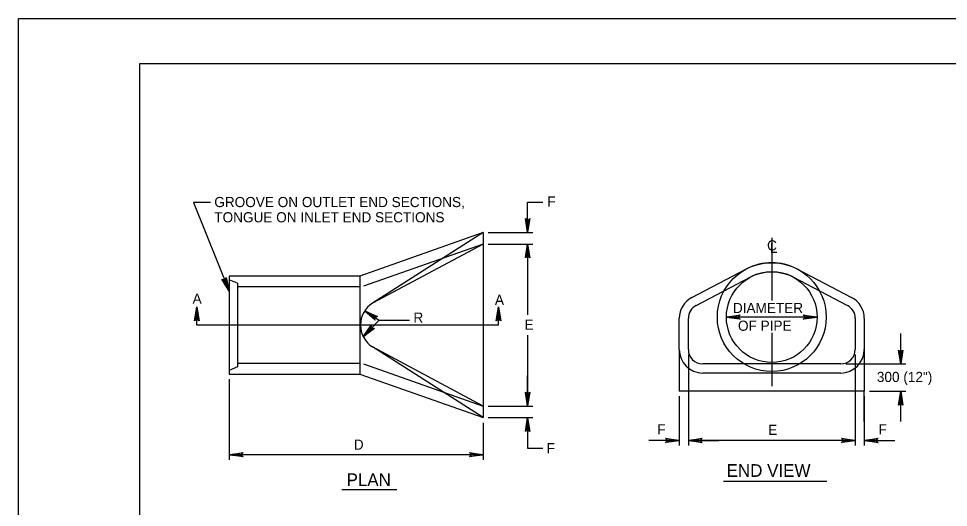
# Model space of a CAD drawing. Extents: x -17 to 888, y -473 to 715.
# Drawn here: x -17.2 to 290.4, y 553.3 to 714.9 of the extents above; entities that cross this region are included whole.
import ezdxf

# ---------------------------------------------------------------- set-up
doc = ezdxf.new("R2010")
doc.units = 0
for name, color, linetype in [('1', 7, 'Continuous'), ('2', 7, 'Continuous'), ('3', 7, 'Continuous'), ('PLT-BNDY', 7, 'Continuous')]:
    doc.layers.add(name, color=color, linetype=linetype)

msp = doc.modelspace()

# ---------------------------------------------------------------- linework, layer by layer
at = {"layer": '1'}
msp.add_lwpolyline([(808.79, 135.89), (808.79, 699.89), (22.79, 699.89), (22.79, 135.89), (808.79, 135.89), (808.79, 162.25), (608.79, 162.25), (608.79, 226.93), (808.79, 226.93), (808.79, 255.89), (608.79, 255.89), (608.79, 135.89), (687.6, 135.89), (687.6, 162.25), (687.6, 135.89), (764.6, 135.89), (764.6, 162.25), (764.6, 149.93), (808.79, 149.93)], dxfattribs=at)
at = {"layer": '2'}
for p, q in [((151.18, 644.17), (151.18, 654.25)), ((136.47, 644.17), (95.67, 629.77)), ((136.47, 644.17), (99.86, 620.83)), ((136.47, 644.17), (136.47, 582.97)), ((138.15, 644.17), (152.86, 644.17)), ((136.47, 640.36), (96.87, 626.38)), ((136.47, 640.36), (99.86, 620.83)), ((138.15, 640.36), (152.86, 640.36)), ((151.18, 640.36), (151.18, 616.93)), ((231.93, 642.4), (231.93, 621.68)), ((205.53, 622.72), (223.61, 632.15)), ((240.26, 632.15), (258.34, 622.72)), ((55.15, 627.37), (52.47, 628.57)), ((206.91, 620.06), (225, 629.49)), ((238.87, 629.49), (256.95, 620.06)), ((41.75, 613.57), (41.75, 619.57)), ((141.53, 613.57), (141.53, 619.57)), ((201.33, 605.51), (201.33, 615.8)), ((204.33, 605.51), (204.33, 615.8)), ((204.33, 605.51), (204.33, 615.8)), ((246.93, 616.19), (216.93, 616.19)), ((259.53, 615.8), (259.53, 605.51)), ((262.53, 615.8), (262.53, 605.51)), ((49.12, 613.57), (41.75, 613.57)), ((137.65, 613.57), (49.12, 613.57)), ((95.67, 613.57), (95.67, 613.57)), ((141.53, 613.57), (137.65, 613.57)), ((151.18, 610.21), (151.18, 586.79)), ((231.93, 611.03), (231.93, 593.4)), ((274.58, 600.71), (274.58, 610.79)), ((136.47, 582.97), (99.86, 606.31)), ((136.47, 586.79), (99.86, 606.31)), ((201.33, 605.51), (201.33, 591.71)), ((204.33, 603.83), (204.33, 573.73)), ((259.53, 603.83), (259.53, 573.73)), ((262.53, 605.51), (262.53, 591.71)), ((55.15, 599.77), (52.47, 598.58)), ((96.87, 600.77), (136.47, 586.79)), ((231.93, 600.71), (209.13, 600.71)), ((254.73, 600.71), (231.93, 600.71)), ((256.41, 600.71), (276.26, 600.71)), ((95.67, 597.37), (136.47, 582.97)), ((151.18, 586.79), (151.18, 596.87)), ((231.93, 597.71), (209.13, 597.71)), ((254.73, 597.71), (209.13, 597.71)), ((254.73, 597.71), (231.93, 597.71)), ((52.47, 595.69), (52.47, 569.03)), ((262.53, 591.71), (201.33, 591.71)), ((262.53, 581.63), (262.53, 591.71)), ((264.21, 591.71), (276.26, 591.71)), ((274.58, 581.63), (274.58, 591.71)), ((201.33, 590.03), (201.33, 573.73)), ((262.53, 590.03), (262.53, 573.73)), ((138.15, 586.79), (152.86, 586.79)), ((136.47, 581.29), (136.47, 569.03)), ((138.15, 582.97), (152.86, 582.97)), ((201.33, 575.41), (191.25, 575.41)), ((241.38, 575.41), (204.33, 575.41)), ((204.33, 575.41), (214.41, 575.41)), ((259.53, 575.41), (241.38, 575.41)), ((259.53, 575.41), (249.45, 575.41)), ((262.53, 575.41), (272.61, 575.41)), ((103.91, 570.71), (52.47, 570.71)), ((136.47, 570.71), (103.91, 570.71))]:
    msp.add_line(p, q, dxfattribs=at)
for points in [[(46.29, 654.05), (40.62, 654.05), (52.47, 624.74)], [(151.18, 654.25), (156.22, 654.25)], [(151.72, 648.53), (151.41, 648.37), (151.18, 644.17), (151.72, 648.53), (151.91, 648.76), (151.18, 644.17), (150.97, 648.37), (150.66, 648.52), (151.18, 644.17), (150.45, 648.76), (150.66, 648.52)], [(150.63, 636), (150.94, 636.16), (151.18, 640.36), (150.63, 636), (150.44, 635.77), (151.18, 640.36), (151.38, 636.16), (151.7, 636.01), (151.18, 640.36), (151.9, 635.77), (151.7, 636.01)], [(51.33, 628.98), (51.1, 628.71), (52.47, 624.74), (51.33, 628.98), (51.42, 629.26), (52.47, 624.74), (50.69, 628.54), (50.35, 628.57), (52.47, 624.74), (50.06, 628.71), (50.35, 628.57)], [(95.67, 629.77), (52.47, 629.77), (52.47, 597.37), (95.67, 597.37)], [(95.67, 629.77), (95.67, 612.76)], [(55.15, 627.37), (55.15, 599.77)], [(95.67, 626.17), (55.15, 626.17)], [(41.21, 615.21), (41.52, 615.38), (41.75, 619.57), (41.21, 615.21), (41.02, 614.99), (41.75, 619.57), (41.96, 615.38), (42.27, 615.23), (41.75, 619.57), (42.48, 614.99), (42.27, 615.23)], [(97.27, 618.27), (102.02, 615.18), (112.1, 615.18)], [(97.27, 618.27), (102.02, 615.18), (112.1, 615.18)], [(100.62, 615.43), (100.66, 615.78), (97.27, 618.27), (100.62, 615.43), (100.71, 615.15), (97.27, 618.27), (100.9, 616.15), (101.19, 616.33), (97.27, 618.27), (101.51, 616.38), (101.19, 616.33)], [(140.99, 615.21), (141.3, 615.38), (141.53, 619.57), (140.99, 615.21), (140.79, 614.99), (141.53, 619.57), (141.74, 615.38), (142.05, 615.23), (141.53, 619.57), (142.26, 614.99), (142.05, 615.23)], [(102.09, 615.18), (96.8, 609.68)], [(221.29, 615.65), (221.13, 615.96), (216.93, 616.19), (221.29, 615.65), (221.52, 615.46), (216.93, 616.19), (221.13, 616.4), (221.28, 616.71), (216.93, 616.19), (221.52, 616.92), (221.28, 616.71)], [(242.58, 616.74), (242.74, 616.43), (246.93, 616.19), (242.58, 616.74), (242.35, 616.93), (246.93, 616.19), (242.74, 615.99), (242.59, 615.67), (246.93, 616.19), (242.35, 615.47), (242.59, 615.67)], [(95.67, 612.76), (95.67, 597.37)], [(100.22, 612.44), (99.88, 612.55), (96.8, 609.68), (100.22, 612.44), (100.52, 612.47), (96.8, 609.68), (99.56, 612.85), (99.45, 613.17), (96.8, 609.68), (99.46, 613.49), (99.45, 613.17)], [(275.13, 605.07), (274.81, 604.91), (274.58, 600.71), (275.13, 605.07), (275.32, 605.29), (274.58, 600.71), (274.37, 604.91), (274.06, 605.06), (274.58, 600.71), (273.85, 605.29), (274.06, 605.06)], [(55.15, 600.97), (95.67, 600.97)], [(151.72, 591.15), (151.41, 590.99), (151.18, 586.79), (151.72, 591.15), (151.91, 591.37), (151.18, 586.79), (150.97, 590.99), (150.66, 591.14), (151.18, 586.79), (150.45, 591.37), (150.66, 591.14)], [(274.03, 587.35), (274.35, 587.52), (274.58, 591.71), (274.03, 587.35), (273.84, 587.13), (274.58, 591.71), (274.79, 587.52), (275.1, 587.37), (274.58, 591.71), (275.31, 587.13), (275.1, 587.37)], [(150.63, 578.62), (150.94, 578.78), (151.18, 582.97), (150.63, 578.62), (150.44, 578.39), (151.18, 582.97), (151.38, 578.78), (151.7, 578.63), (151.18, 582.97), (151.9, 578.39), (151.7, 578.63)], [(151.18, 582.97), (151.18, 572.89)], [(196.98, 575.96), (197.14, 575.64), (201.33, 575.41), (196.98, 575.96), (196.75, 576.15), (201.33, 575.41), (197.14, 575.2), (196.99, 574.89), (201.33, 575.41), (196.75, 574.68), (196.99, 574.89)], [(208.69, 574.86), (208.53, 575.18), (204.33, 575.41), (208.69, 574.86), (208.92, 574.67), (204.33, 575.41), (208.53, 575.62), (208.68, 575.93), (204.33, 575.41), (208.92, 576.14), (208.68, 575.93)], [(255.18, 575.96), (255.34, 575.64), (259.53, 575.41), (255.18, 575.96), (254.95, 576.15), (259.53, 575.41), (255.34, 575.2), (255.19, 574.89), (259.53, 575.41), (254.95, 574.68), (255.19, 574.89)], [(266.89, 574.86), (266.73, 575.18), (262.53, 575.41), (266.89, 574.86), (267.12, 574.67), (262.53, 575.41), (266.73, 575.62), (266.88, 575.93), (262.53, 575.41), (267.12, 576.14), (266.88, 575.93)], [(151.18, 572.89), (156.22, 572.89)], [(56.83, 570.16), (56.66, 570.48), (52.47, 570.71), (56.83, 570.16), (57.05, 569.97), (52.47, 570.71), (56.66, 570.92), (56.81, 571.23), (52.47, 570.71), (57.05, 571.44), (56.81, 571.23)], [(132.11, 571.26), (132.27, 570.94), (136.47, 570.71), (132.11, 571.26), (131.89, 571.45), (136.47, 570.71), (132.27, 570.5), (132.12, 570.19), (136.47, 570.71), (131.89, 569.98), (132.12, 570.19)]]:
    msp.add_lwpolyline(points, dxfattribs=at)
for radius in [18, 15]:
    msp.add_circle((231.93, 616.19), radius, dxfattribs=at)
for centre, radius, start, end in [((231.93, 616.19), 18, 62.4472, 117.5528), ((231.93, 616.19), 15, 62.4472, 117.5528), ((209.13, 615.8), 7.8, 117.5525, 180), ((254.73, 615.8), 7.8, 0, 62.4475), ((104.49, 613.57), 8.61, 122.5176, 237.4824), ((209.13, 615.8), 4.8, 117.5525, 180), ((209.13, 615.8), 4.8, 117.5525, 180), ((254.73, 615.8), 4.8, 0, 62.4475), ((209.13, 605.51), 7.8, 180, 270), ((209.13, 605.51), 4.8, 180, 270), ((254.73, 605.51), 4.8, 270, 0), ((254.73, 605.51), 7.8, 270, 0)]:
    msp.add_arc(centre, radius, start, end, dxfattribs=at)
at = {"layer": '3'}
for p, q in [((216, 561.99), (250.12, 561.99)), ((89.76, 559.17), (107.92, 559.17))]:
    msp.add_line(p, q, dxfattribs=at)
at = {"layer": 'PLT-BNDY'}
msp.add_lwpolyline([(-17.21, 714.89), (823.79, 714.89), (823.79, 120.89), (-17.21, 120.89)], close=True, dxfattribs=at)

# ---------------------------------------------------------------- texts
at = {"layer": '3'}
for s, height, p in [('GROOVE ON OUTLET END SECTIONS,', 3.36, (47.53, 652.56)), ('F', 3.36, (157.7, 652.75)), ('TONGUE ON INLET END SECTIONS', 3.36, (47.53, 647.52)), ('C', 3.36, (230.37, 638.23)), ('L', 3.36, (231.26, 637.42)), ('A', 3.36, (40.35, 620.63)), ('A', 3.36, (140.35, 620.24)), ('DIAMETER', 3.36, (219.07, 617.53)), ('R', 3.36, (113.4, 614.35)), ('E', 3.36, (150.15, 612.04)), ('OF PIPE', 3.36, (220.75, 611.67)), ('300 (12")', 3.36, (266.7, 594.73)), ('F', 3.36, (194.08, 577.38)), ('E', 3.36, (230.75, 577.23)), ('F', 3.36, (267.24, 577.38)), ('D', 3.36, (93.67, 572.36)), ('F', 3.36, (157.44, 571.19)), ('END VIEW', 4.2, (216.98, 563.37)), ('PLAN', 4.2, (91.27, 560.31))]:
    msp.add_text(s, height=height, dxfattribs=at).set_placement(p)

doc.saveas('drawing.dxf')
